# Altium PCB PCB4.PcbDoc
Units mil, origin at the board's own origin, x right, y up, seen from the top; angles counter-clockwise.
Board outline 6000 x 4000 mil, 2 copper layers (Top Layer, Bottom Layer); 90 components, 74 nets, 378 pads, 0 vias.
Unrouted connection lines stored in the file: 247.
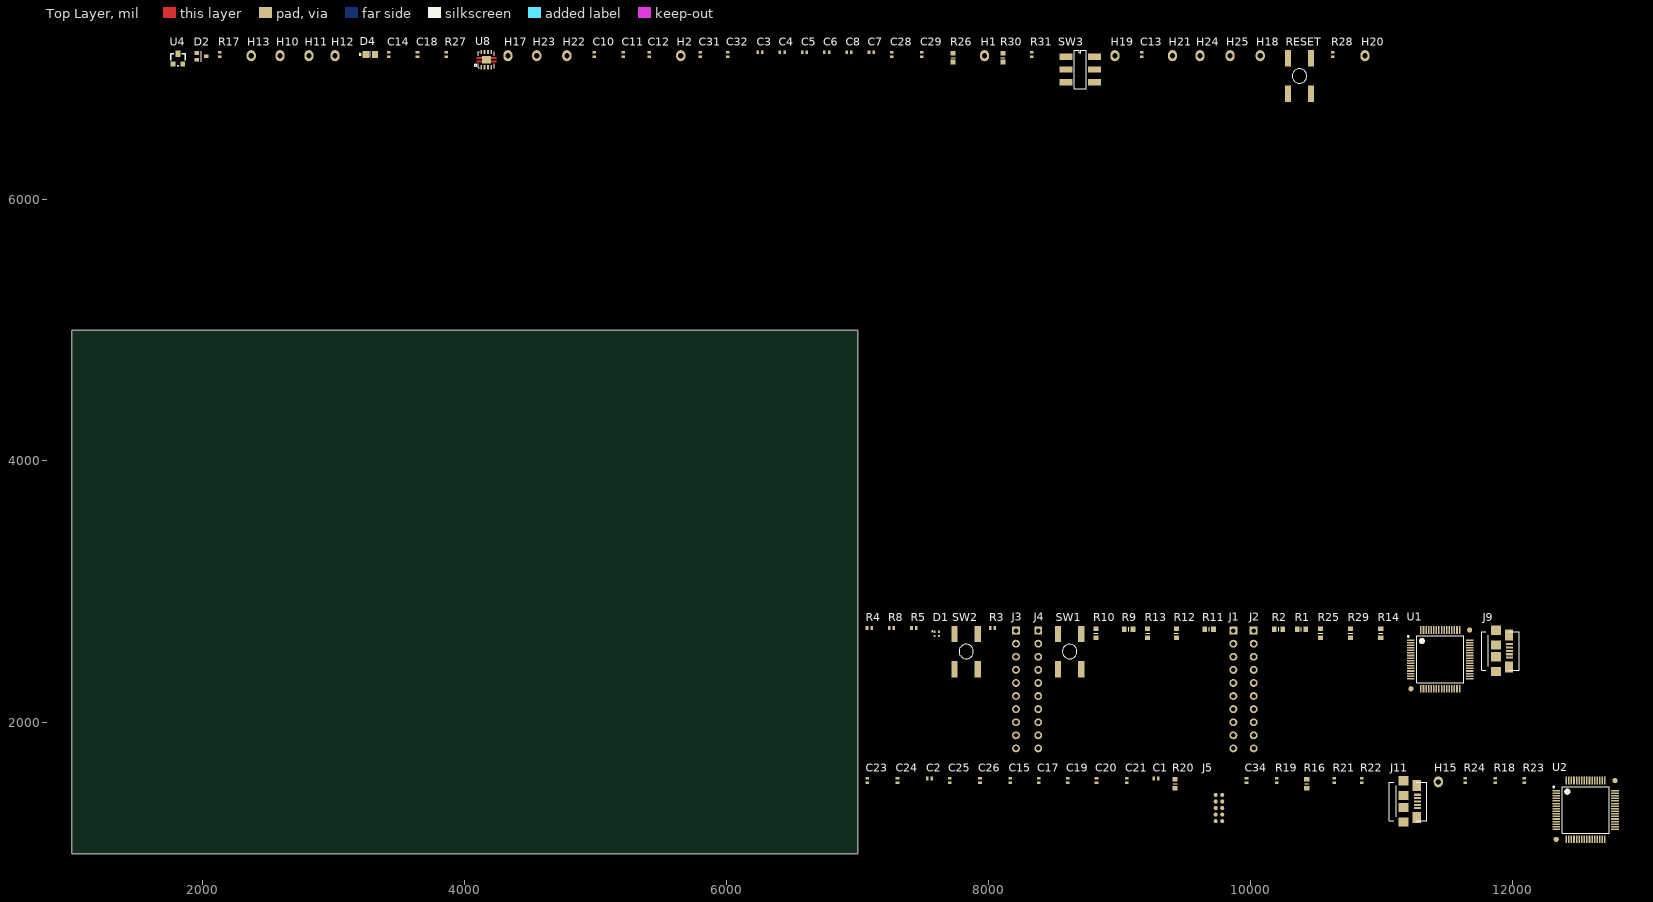
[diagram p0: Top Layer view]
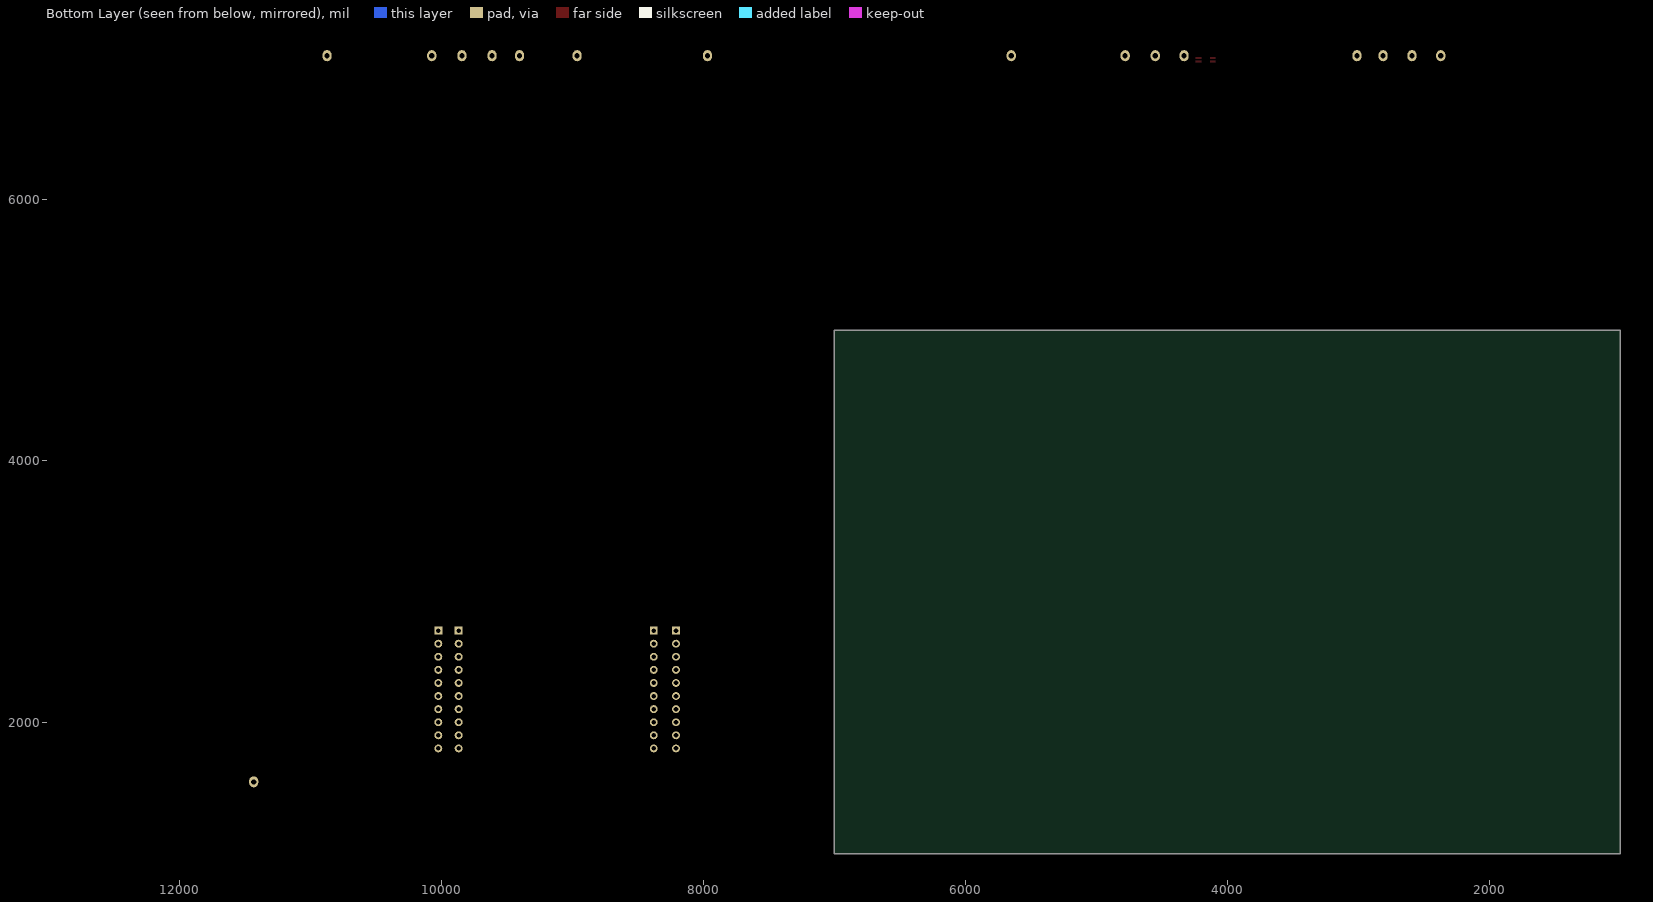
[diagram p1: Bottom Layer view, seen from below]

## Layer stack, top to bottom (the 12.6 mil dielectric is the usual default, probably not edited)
Top Solder: solder mask 0.4, Solder Resist, Dk 3.5
Top Layer: signal copper 1.4
Dielectric 1: dielectric 12.6, FR-4, Dk 4.8
Bottom Layer: signal copper 1.4
Bottom Solder: solder mask 0.4, Solder Resist, Dk 3.5

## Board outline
1000,1000 7000,1000 7000,5000 1000,5000

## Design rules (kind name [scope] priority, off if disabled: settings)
Clearance [All] p1: gap=10
PolygonConnect [All] p1: connectstyle=Relief reliefconductorwidth=10 reliefentries=4 polygonreliefangle="90 Angle" airgapwidth=10
RoomDefinition POWER [InComponentClass('POWER')] p1: confinementstyle=ConfineIn formatcopy=TRUE lockcomponents=FALSE outline 1730,6730 11025,6730 11025,7250 1730,7250
RoomDefinition IO [InComponentClass('IO')] p2: confinementstyle=ConfineIn formatcopy=TRUE lockcomponents=FALSE outline 7045,1755 12060,1755 12060,2855 7045,2855
RoomDefinition ICDI [InComponentClass('ICDI')] p3: confinementstyle=ConfineIn formatcopy=TRUE lockcomponents=FALSE outline 7045,1065 12830,1065 12830,1705 7045,1705
RoutingVias [All] p1: holewidth=28 width=50 viastyle="Through Hole" minholewidth=28 minwidth=50 maxholewidth=28 maxwidth=50
SolderMaskExpansion [All] p1: expansion=4
Width [All] p1: maxlimit=10 minlimit=10 preferedwidth=10
30 further rules are at their usual default settings.

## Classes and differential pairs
component class ICDI: C1 C2 C9 C15 C17 C19 C20 C21 C23 C24 C25 C26 C34 H14 H15 J5 J11 R16 R18 R19 R20 R21 R22 R23 R24 U2 Y5
component class IO: D1 H3 H4 H5 H6 H7 H8 H9 H91 J1 J2 J3 J4 J9 Q1 Q2 Q3 R1 R2 R3 R4 R5 R8 R9 R10 R11 R12 R13 R14 R25 R29 SW1 SW2 U1
component class POWER: C3 C4 C5 C6 C7 C8 C10 C11 C12 C13 C14 C18 C22 C28 C29 C31 C32 D2 D4 H1 H2 H10 H11 H12 H13 H17 H18 H19 H20 H21 H22 H23 H24 H25 R17 R26 R27 R28 R30 R31 RESET SW3 U4 U8 Y1 Y2

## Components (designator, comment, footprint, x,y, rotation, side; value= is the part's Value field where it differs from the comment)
C1 "CAPC0402" CAPC0402N 9280,1575 r0 top
C2 "CAPC0402" CAPC0402N 7550,1575 r0 top
C3 "CAPC0402" CAPC0402N 6255,7120 r0 top
C4 "CAPC0402" CAPC0402N 6425,7120 r0 top
C5 "CAPC0402" CAPC0402N 6595,7120 r0 top
C6 "CAPC0402" CAPC0402N 6765,7120 r0 top
C7 "CAPC0402" CAPC0402N 7105,7120 r0 top
C8 "CAPC0402" CAPC0402N 6935,7120 r0 top
C10 "CAPC0402" CAPC0402N 4990,7105 r90 top
C11 "CAPC0402" CAPC0402N 5210,7105 r90 top
C12 "CAPC0402" CAPC0402N 5410,7105 r90 top
C13 "CAPC0402" CAPC0402N 9170,7105 r90 top
C14 "CAPC0402" CAPC0402N 3420,7105 r90 top
C15 "CAPC0402" CAPC0402N 8165,1560 r90 top
C17 "CAPC0402" CAPC0402N 8385,1560 r90 top
C18 "CAPC0402" CAPC0402N 3640,7105 r90 top
C19 "CAPC0402" CAPC0402N 8605,1560 r90 top
C20 "CAPC0402" CAPC0402N 8825,1560 r90 top
C21 "CAPC0402" CAPC0402N 9055,1560 r90 top
C23 "CAPC0402" CAPC0402N 7075,1560 r90 top
C24 "CAPC0402" CAPC0402N 7305,1560 r90 top
C25 "CAPC0402" CAPC0402N 7705,1560 r90 top
C26 "CAPC0402" CAPC0402N 7935,1560 r90 top
C28 "CAPC0402" CAPC0402N 7260,7105 r90 top
C29 "CAPC0402" CAPC0402N 7490,7105 r90 top
C31 "CAPC0402" CAPC0402N 5800,7105 r90 top
C32 "CAPC0402" CAPC0402N 6010,7105 r90 top
C34 "CAPC0402" CAPC0402N 9970,1560 r90 top
D1 "RGB_LED_0404_COMA" 0404_QUAD 7605,2680 r0 top
D2 "DIO_BAT54_CC" SC70-3 1990,7090 r0 top
D4 "LED-0805" DIOC0805N 3280,7105 r0 top
H1 "HDR-ENDLINE" PAD70H39 7970,7095 r0 top
H2 "HDR-ENDLINE" PAD70H39 5650,7095 r0 top
H10 "HDR-ENDLINE" PAD70H39 2590,7095 r0 top
H11 "HDR-ENDLINE" PAD70H39 2810,7095 r0 top
H12 "HDR-ENDLINE" PAD70H39 3010,7095 r0 top
H13 "HDR-ENDLINE" PAD70H39 2370,7095 r0 top
H15 "HDR-ENDLINE" PAD70H39 11435,1550 r0 top
H17 "HDR-ENDLINE" PAD70H39 4330,7095 r0 top
H18 "HDR-ENDLINE" PAD70H39 10075,7095 r0 top
H19 "HDR-ENDLINE" PAD70H39 8965,7095 r0 top
H20 "HDR-ENDLINE" PAD70H39 10875,7095 r0 top
H21 "HDR-ENDLINE" PAD70H39 9405,7095 r0 top
H22 "HDR-ENDLINE" PAD70H39 4780,7095 r0 top
H23 "HDR-ENDLINE" PAD70H39 4550,7095 r0 top
H24 "HDR-ENDLINE" PAD70H39 9615,7095 r0 top
H25 "HDR-ENDLINE" PAD70H39 9845,7095 r0 top
J1 "CON_110_100" TSW-110-100 9870,2705 r0 top
J2 "CON_110_100" TSW-110-100 10025,2705 r0 top
J3 "CON_110_100" TSW-110-100 8210,2705 r0 top
J4 "CON_110_100" TSW-110-100 8380,2705 r0 top
J5 "TC2050-IDC-NL" TC2050-IDC-NL 9760,1350 r90 top
J9 "CON-USB-MICROAB" CON-USB-MICRO-S 11875,2550 r0 top
J11 "CON-USB-MICROB" CON-USB-MICRO-S 11170,1400 r0 top
R1 "RESC0603" RESC0603N 10390,2715 r0 top
R2 "RESC0603" RESC0603N 10215,2715 r0 top
R3 "RESC0402" RESC0402N 8030,2725 r0 top
R4 "RESC0402" RESC0402N 7090,2725 r0 top
R5 "RESC0402" RESC0402N 7430,2725 r0 top
R8 "RESC0402" RESC0402N 7260,2725 r0 top
R9 "RESC0603" RESC0603N 9070,2715 r0 top
R10 "RESC0603" RESC0603N 8820,2685 r90 top
R11 "RESC0603" RESC0603N 9685,2715 r0 top
R12 "RESC0603" RESC0603N 9435,2685 r90 top
R13 "RESC0603" RESC0603N 9215,2685 r90 top
R14 "RESC0603" RESC0603N 10995,2685 r90 top
R16 "RESC0603" RESC0603N 10430,1535 r90 top
R17 "RESC0402" RESC0402N 2130,7105 r90 top
R18 "RESC0402" RESC0402N 11870,1560 r90 top
R19 "RESC0402" RESC0402N 10200,1560 r90 top
R20 "RESC0603" RESC0603N 9425,1535 r90 top
R21 "RESC0402" RESC0402N 10640,1560 r90 top
R22 "RESC0402" RESC0402N 10850,1560 r90 top
R23 "RESC0402" RESC0402N 12090,1560 r90 top
R24 "RESC0402" RESC0402N 11640,1560 r90 top
R25 "RESC0603" RESC0603N 10535,2685 r90 top
R26 "RESC0603" RESC0603N 7730,7080 r90 top
R27 "RESC0402" RESC0402N 3860,7105 r90 top
R28 "RESC0402" RESC0402N 10630,7105 r90 top
R29 "RESC0603" RESC0603N 10765,2685 r90 top
R30 "RESC0603" RESC0603N 8110,7080 r90 top
R31 "RESC0402" RESC0402N 8330,7105 r90 top
RESET "SW-EVQQ2" SW-EVQQ2 10375,6940 r90 top
SW1 "SW-EVQQ2" SW-EVQQ2 8620,2545 r90 top
SW2 "SW-EVQQ2" SW-EVQQ2 7830,2545 r90 top
SW3 "SW_DPDT" SW_JS202011SCQN 8700,6990 r0 top
U1 "TM4C123G" QFP50P1200X1200X160-64N 11450,2485 r0 top
U2 "TM4C123G" QFP50P1200X1200X160-64N 12560,1335 r0 top
U4 "TLV803" SOT23 1810,7070 r0 top
U8 "TPS73633DRB" TI-DRB-SON8 4165,7065 r0 top

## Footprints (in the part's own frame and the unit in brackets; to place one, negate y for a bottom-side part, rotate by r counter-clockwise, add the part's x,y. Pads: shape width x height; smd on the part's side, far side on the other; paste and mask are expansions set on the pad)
0404_QUAD [mm]
  rrect0% 0.45x0.45 smd: 1(-0.423,0.423) 2(0.423,0.423) 3(0.423,-0.423) 4(-0.423,-0.423)
  silkscreen extent -0.98,0.41 -0.82,0.56
CAPC0402N [mm]
  rect 0.5x0.7 smd: 1(-0.45,0) 2(0.45,0)
CON-USB-MICRO-S [mm]
  rect 1.35x0.4 smd: 1(2.675,1.3) 2(2.675,0.65) 3(2.675,0) 4(2.675,-0.65) 5(2.675,-1.3)
  rect 1.6x2.1 smd: 6(2.55,3.1) 7(2.55,-3.1)
  rect 1.9x1.8 smd: 8(0,4) 9(0,-4) 10(0,1.15) 11(0,-1.15)
  silkscreen extent -2.75,-3.75 4.5,3.75
DIOC0805N [mm]
  rect 1.2x1.4 smd: 1(-0.9,0) 2(0.9,0)
  silkscreen extent -2.2,-0.6 0,0.6
PAD70H39 [mil]
  oval 70x85 / inner round 70 / far side oval 70x85 hole 39: 1(0,0)
QFP50P1200X1200X160-64N [mm]
  rect 1.5x0.3 smd: 1(-5.7,3.75) 2(-5.7,3.25) 3(-5.7,2.75) 4(-5.7,2.25) 5(-5.7,1.75) 6(-5.7,1.25) 7(-5.7,0.75) 8(-5.7,0.25) 9(-5.7,-0.25) 10(-5.7,-0.75) 11(-5.7,-1.25) 12(-5.7,-1.75) 13(-5.7,-2.25) 14(-5.7,-2.75) 15(-5.7,-3.25) 16(-5.7,-3.75) 33(5.7,-3.75) 34(5.7,-3.25) 35(5.7,-2.75) 36(5.7,-2.25) 37(5.7,-1.75) 38(5.7,-1.25) 39(5.7,-0.75) 40(5.7,-0.25) 41(5.7,0.25) 42(5.7,0.75) 43(5.7,1.25) 44(5.7,1.75) 45(5.7,2.25) 46(5.7,2.75) 47(5.7,3.25) 48(5.7,3.75)
  rect 0.3x1.5 smd: 17(-3.75,-5.7) 18(-3.25,-5.7) 19(-2.75,-5.7) 20(-2.25,-5.7) 21(-1.75,-5.7) 22(-1.25,-5.7) 23(-0.75,-5.7) 24(-0.25,-5.7) 25(0.25,-5.7) 26(0.75,-5.7) 27(1.25,-5.7) 28(1.75,-5.7) 29(2.25,-5.7) 30(2.75,-5.7) 31(3.25,-5.7) 32(3.75,-5.7) 49(3.75,5.7) 50(3.25,5.7) 51(2.75,5.7) 52(2.25,5.7) 53(1.75,5.7) 54(1.25,5.7) 55(0.75,5.7) 56(0.25,5.7) 57(-0.25,5.7) 58(-0.75,5.7) 59(-1.25,5.7) 60(-1.75,5.7) 61(-2.25,5.7) 62(-2.75,5.7) 63(-3.25,5.7) 64(-3.75,5.7)
  round 1 smd mask+0.5: 65(-5.7,-5.7) 66(5.7,5.7)
  Top Layer pour cut-out: -4.7,-5.7 -4.7,-5.602 -4.738,-5.408 -4.814,-5.226 -4.923,-5.063 -5.063,-4.923 -5.226,-4.814 -5.408,-4.738 -5.602,-4.7 -5.7,-4.7 -5.798,-4.7 -5.992,-4.738 -6.174,-4.814 -6.337,-4.923 -6.477,-5.063 -6.586,-5.226 -6.662,-5.408 -6.7,-5.602 -6.7,-5.7 -6.7,-5.798 -6.662,-5.992 -6.586,-6.174 -6.477,-6.337 -6.337,-6.477 -6.174,-6.586 -5.992,-6.662 -5.798,-6.7 -5.7,-6.7 -5.602,-6.7 -5.408,-6.662 -5.226,-6.586 -5.063,-6.477 -4.923,-6.337 -4.814,-6.174 -4.738,-5.992 -4.7,-5.798 -4.7,-5.7
  Top Layer pour cut-out: 6.7,5.7 6.7,5.798 6.662,5.992 6.586,6.174 6.477,6.337 6.337,6.477 6.174,6.586 5.992,6.662 5.798,6.7 5.7,6.7 5.602,6.7 5.408,6.662 5.226,6.586 5.063,6.477 4.923,6.337 4.814,6.174 4.738,5.992 4.7,5.798 4.7,5.7 4.7,5.602 4.738,5.408 4.814,5.226 4.923,5.063 5.063,4.923 5.226,4.814 5.408,4.738 5.602,4.7 5.7,4.7 5.798,4.7 5.992,4.738 6.174,4.814 6.337,4.923 6.477,5.063 6.586,5.226 6.662,5.408 6.7,5.602 6.7,5.7
  silkscreen extent -6.32,-4.55 4.55,4.57
RESC0402N [mm]
  rect 0.5x0.7 smd: 1(-0.45,0) 2(0.45,0)
RESC0603N [mm]
  rect 0.9x1 smd: 1(-0.85,0) 2(0.85,0)
  silkscreen extent 0,-0.4 0,0.4
SC70-3 [mm]
  rect 0.9x0.7 smd: 1(-0.95,0.65) 2(-0.95,-0.65) 3(0.95,0)
  silkscreen extent 0,-1 0,1
SOT23 [mil]
  rect 36x36 smd: 1(-37.5,-39) 2(37.5,-39)
  rect 36x50 smd: 3(0,41)
  silkscreen extent -55,-50 55,40
SW-EVQQ2 [mm]
  rect 3.2x1.2 smd: 1(-3.4,2.25) 2(-3.4,-2.25) 3(3.4,2.25) 4(3.4,-2.25)
  silkscreen extent -1.4,-1.4 1.4,1.4
SW_JS202011SCQN [mil]
  rect 98.5x48 smd: 1(-108.25,98) 2(-108.25,0) 3(-108.25,-98) 4(108.25,-98) 5(108.25,0) 6(108.25,98)
  silkscreen extent -45,-147 45,147
TC2050-IDC-NL [mil]
  round 31 smd paste-15.5: 1(-100,-25) 2(-50,-25) 3(0,-25) 4(50,-25) 5(100,-25) 6(100,25) 7(50,25) 8(0,25) 9(-50,25) 10(-100,25)
  round 0 hole 39 unplated: 11(-150,0) 12(150,-40) 13(150,40)
  Top Layer pour cut-out: -100,-14 100,-14 100,13 -100,13 -100,-14
TI-DRB-SON8 [mm]
  rect 0.35x0.85 smd: 1(-0.975,-1.475) 2(-0.325,-1.475) 3(0.325,-1.475) 4(0.975,-1.475) 5(0.975,1.475) 6(0.325,1.475) 7(-0.325,1.475) 8(-0.975,1.475)
  rrect1% 1.75x1.5 smd paste-0.1: 9(0,0)
  round 0 all layers, no hole: 10(0,0) 11(0,0) 12(0,0) 13(0,0)
  Top Layer region: -0.875,0.465 -1.9,0.465 -1.9,0.185 -0.875,0.185 -0.875,0.465
  Top Layer region: -0.875,-0.185 -1.9,-0.185 -1.9,-0.465 -0.875,-0.465 -0.875,-0.185
  Top Layer region: 1.9,0.465 0.875,0.465 0.875,0.185 1.9,0.185 1.9,0.465
  Top Layer region: 1.9,-0.185 0.875,-0.185 0.875,-0.465 1.9,-0.465 1.9,-0.185
  silkscreen extent -2.32,-1.58 1.58,1.58
TSW-110-100 [mil]
  rect 60x60 / inner round 60 / far side rect 60x60 hole 35: 1(0,0)
  round 60 hole 35: 2(0,-100) 3(0,-200) 4(0,-300) 5(0,-400) 6(0,-500) 7(0,-600) 8(0,-700) 9(0,-800) 10(0,-900)

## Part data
C1 C2 C3 C4 C5 C6 C7 C8 C10 C11 C12 C14 C15 C17 C18 C19 C20 C21 C23 C24 C25 C26 C28 C29 C31 C32: "SURFACE MOUNT CAPACITOR 0402"
C13 C34: "OMIT"
D4: "SMT LED IN 0805 PACK"
J9 J11: "Connector, USB micro AB Receptacle SMT"
R3 R4 R5 R8 R17 R18 R19 R21 R22 R23 R24 R27 R28 R31: "Resistor,Chip;1.00mm L X 0.5mm W X 0.35mm H"
R20 R26: "Resistor,Chip;1.60mm L X 0.83mm W X 0.60mm H"
RESET SW1 SW2: "Switch, Tact 6mm SMT, 50gf"

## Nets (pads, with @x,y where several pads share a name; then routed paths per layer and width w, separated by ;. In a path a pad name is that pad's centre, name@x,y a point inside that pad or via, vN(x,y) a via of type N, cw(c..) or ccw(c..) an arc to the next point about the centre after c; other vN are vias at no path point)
+3.3V: C1.1 C15.1 C17.1 C19.1 C20.1 C21.1 H22.1 H25.1 J1.1 R17.1 R19.1 R21.1 R22.1 R27.1 R30.2 U2.2 U2.11 U2.26 U2.37 U2.42 U2.45 U2.54 U8.1
+ICDI_VBUS: H19.1 J11.1 R24.2 SW3.3 SW3.4
+MCU_PWR: C3.1 C4.1 C5.1 C6.1 C7.1 C8.1 H24.1 R18.1 R23.1 R28.1 R30.1 R31.1 U1.2 U1.11 U1.26 U1.37 U1.42 U1.54
+MCU_VDDC: C10.1 C11.1 C12.1 H2.1 U1.25 U1.56
+USB_VBUS: H18.1 J9.1 R29.1 SW3.1 SW3.6
+VBUS: C14.1 D1.1 H17.1 H23.1 J3.1 SW3.2 SW3.5 U4.3 U8.5 U8.8
\EXTDBG\: U2.24
\HIB: H1.1 U1.33
\TARGETRST\: C13.1 D2.1 H20.1 J2.5 R28.2 RESET.2 RESET.4 U1.38 U2.23
\WAKE: H21.1 R8.1 R31.2 U1.32
DEBUG_PC0/TCK/SWCLK: U1.52
DEBUG_PC1/TMS/SWDIO: U1.51
DEBUG_PC2/TDI: U1.50
DEBUG_PC3/TDO/SWO: U1.49
GND: C1.2 C2.2 C3.2 C4.2 C5.2 C6.2 C7.2 C8.2 C10.2 C11.2 C12.2 C13.2 C14.2 C15.2 C17.2 C18.2 C19.2 C20.2 C21.2 C23.2 C24.2 C25.2 C26.2 C31.2 C32.2 C34.2 D4.1 H10.1 H11.1 H12.1 H13.1 J2.1 J3.2 J5.3 J5.5 J5.9 J9.5 J11.5 R14.2 R16.2 RESET.1 RESET.3 SW1.2 SW1.4 SW2.2 SW2.4 U1.3 U1.12 U1.27 U1.39 U1.55 U2.3 U2.12 U2.27 U2.32 U2.34 U2.35 U2.39 U2.55 U4.1 U8.4 U8.9
ICDI_\RST\: C34.1 D2.2 J5.10 R19.2 U2.38
ICDI_TCK: J5.4 R21.2 U2.52
ICDI_TDI: J5.8 U2.50
ICDI_TDO: J5.6 U2.49
ICDI_TMS: J5.2 R22.2 U2.51
LED_B: R11.2
LED_G: R12.2
LED_R: R2.2
NetC2_1: C2.1 C23.1 C24.1 U2.25 U2.56
NetC18_1: C18.1 U8.3
NetC25_1: C25.1 R20.1
NetC26_1: C26.1 U2.40
NetC28_1: C28.1 U1.34
NetC28_2: C28.2 C29.1 U1.35
NetC29_2: C29.2 U1.36
NetC31_1: C31.1 R26.1
NetC32_1: C32.1 U1.40
NetD1_2: D1.2 R3.2
NetD1_3: D1.3 R5.2
NetD1_4: D1.4 R4.2
NetD2_3: D2.3 R17.2 U4.2
NetD4_2: D4.2 R27.2
NetH15_1: H15.1 U2.64
NetJ9_4: J9.4 R25.2
NetJ9_6: J9.6 J9.7 J9.8 J9.9 R14.1
NetJ11_2: J11.2 U2.43
NetJ11_3: J11.3 U2.44
NetJ11_6: J11.6 J11.7 J11.8 J11.9 R16.1
NetQ1_C: R3.1
NetQ2_C: R4.1
NetQ3_C: R5.1
NetR20_2: R20.2 U2.41
NetR24_1: R24.1 U2.46
NetR26_2: R26.2 U1.41
PA0/U0RX_VCP_TXD: U1.17
PA1/U0TX_VCP_RXD: U1.18
PA2: J1.10 J2.10 U1.19 U1.24
PA3: J1.9 J2.9 U1.20 U1.23
PA4: J1.8 J2.8 U1.21 U1.22
PB0: J1.3 J2.3 R25.1 U1.9 U1.45
PB1: J1.4 J2.4 R1.1 R29.2 U1.28 U1.46
PB2: J1.2 J2.2 U1.47 U1.57
PB3: J3.3 J4.3 R9.1 U1.48 U1.61
PB4: J1.7 J2.7 R9.2 U1.1 U1.58
PB7: J1.6 J2.6 R10.2 U1.4 U1.60
PC4: J3.4 J4.4 R10.1 U1.16 U1.62
PC5: J3.5 J4.5 U1.15 U1.63
PC6: J3.6 J4.6 U1.14 U1.64
PC7: J3.7 J4.7 U1.8 U1.13
PD6: J3.8 J4.8 U1.7 U1.53
PD7: J3.9 J4.9 U1.6 U1.10
PE4: J1.5 U1.59
PF1: J3.10 J4.10 R2.1 R13.1 U1.5 U1.29
PF2: J4.1 R11.1 U1.30
PF3: J4.2 R12.1 U1.31
USB_DM: J9.2 U1.43
USB_DP: J9.3 U1.44
USR_SW1: R13.2 SW1.1 SW1.3
USR_SW2: R1.2 R8.2 SW2.1 SW2.3
pads on no net: J5.1 J5.7 J5.11 J5.12 J5.13 J9.10 J9.11 J11.4 J11.10 J11.11 R18.2 R23.2 U1.65 U1.66 U2.1 U2.4 U2.5 U2.6 U2.7 U2.8 U2.9 U2.10 U2.13 U2.14 U2.15 U2.16 U2.17 U2.18 U2.19 U2.20 U2.21 U2.22 U2.28 U2.29 U2.30 U2.31 U2.33 U2.36 U2.47 U2.48 U2.53 U2.57 U2.58 U2.59 U2.60 U2.61 U2.62 U2.63 U2.65 U2.66 U8.2 U8.6 U8.7 U8.10 U8.11 U8.12 U8.13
